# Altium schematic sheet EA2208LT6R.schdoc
size 127 x 101 mm
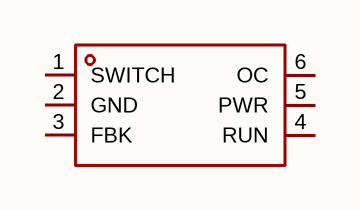
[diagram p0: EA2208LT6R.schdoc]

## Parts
U?  ea2208lt6r  [SOT-23-6_L2.9-W1.6-P0.95-LS2.8-BR]  (value not drawn)

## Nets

Not connected (* = marked no-connect by the designer): U? 1(SWITCH) 2(GND) 3(FBK) 4(RUN) 5(PWR) 6(OC)

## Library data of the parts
U? = ea2208lt6r: 功能类型:升压型;工作电压:2.2V~16V;输出电压:600mV~16V;输出电流:2.5A;输出类型:可调;; Manufacturer: everanalog(申风); AddInBom: yes; ModelId: 18da8f6c14a34920b3e136b5c401a119; ModelName: SOT-23-6_L2.9-W1.6-H1.5-LS2.8-P0.95; ModelTransform: 110.73671,114.173,0,180,0,0,0.001,-0.003,0; Function: 升压型; Output Current: 2.5A; Frequency - Switching: 1.2MHz; Synchronous Rectifier: 否; Number of Outputs: 1; Topology: 升压式; Quiescent Current: 100uA；1mA; Switch tube (built-in/external): 内置; Output Type: 可调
